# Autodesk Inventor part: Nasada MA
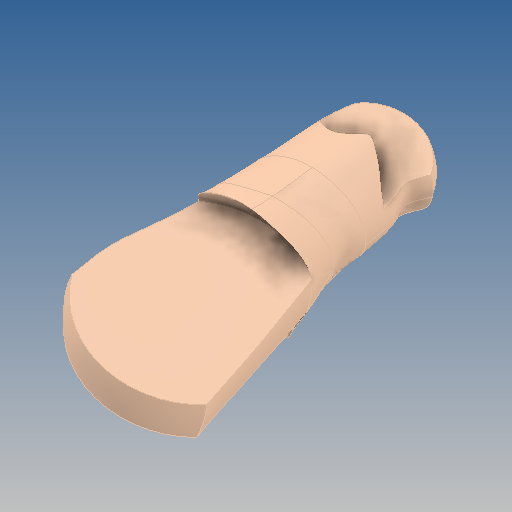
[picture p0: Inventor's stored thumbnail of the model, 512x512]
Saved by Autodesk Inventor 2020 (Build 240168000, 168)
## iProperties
Created: 2019-10
Part Number: Nasada MA
Material: GFRP
Document SubType Name: Modeling
Designer: yello
Density: 1.75 g/cm^3
Appearance: Default
Author: yello
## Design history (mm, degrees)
feature "Nasada MA"
body "Solid1"
